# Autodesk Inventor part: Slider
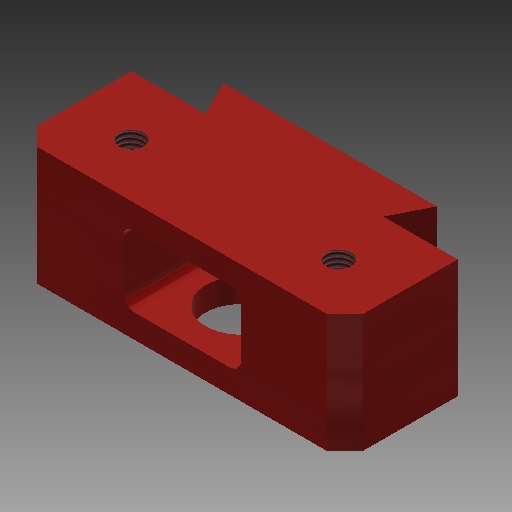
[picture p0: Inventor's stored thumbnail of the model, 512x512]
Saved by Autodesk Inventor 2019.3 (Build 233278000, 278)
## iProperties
Created: 2011-02
Part Number: Slider
Material: Glass
Document SubType Name: Modeling
Designer: landrews
Density: 2.18 g/cm^3
Appearance: Orange-Red
Mass: 44.0724 g
Surface Area: 68.5197 cm^2
Volume: 20.2167 cm^3
Author: landrews
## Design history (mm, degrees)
sketch "Sketch1"
  geometry: L1 (-27.5, 6)-(-15, 6); L2 (-15, 6)-(-18, 0); L3 (-27.5, 25)-(-27.5, 6); L4 (-27.5, 25)-(0, 25); L5 (-18, 0)-(0, 0); L6 (0, -5)-(0, 30) reference; L7 (38.5, 0)-(-38.5, 0) reference; L8 (27.5, 6)-(15, 6); L9 (15, 6)-(18, 0); L10 (27.5, 25)-(27.5, 6); L11 (27.5, 25)-(0, 25); L12 (18, 0)-(0, 0)
  constraints: 20 end point, 4 symmetric about line, 3 point on line, 2 horizontal
  dimensions: "d9" = 19 distance of L3.start L1.start; "d10" = 25 distance between parallel lines of L5 L4; "d11" = 27.5 distance between parallel lines of L6 L3; "d17" = 12.5 distance of L1.start L1.end; "d19" = 9.5 distance from line of L3 L2.end
extrude "Extrusion1" new body sketch "Sketch1" stored distance "d13" = 20; taper "d14" = 0 deg
sketch "Sketch2"
  geometry: L1 (18, 0)-(-18, 0) reference; L2 (-27.5, 25)-(27.5, 25) reference; 3 further points
  constraints: 1 midpoint, 1 vertical alignment
  dimensions: "d20" = 10 distance from line of L2 point (0, 15)
hole "Hole1" sketch "Sketch2" at (0, 15) diameter "d21" = 12; stored, may be unused: countersink angle "d25" = 90 deg, drill point angle "d27" = 118 deg; dims "d22" = 6, "d23" = 4, "d24" = 2, "d26" = 8
sketch "Sketch3"
  geometry: L1 (19.5, -16)-(35.5, -16); L2 (35.5, -4)-(19.5, -4); L3 (37.5, -14)-(37.5, -6); L4 (17.5, -6)-(17.5, -14); L5 (-11, -10)-(66, -10) reference; L6 (27.5, 4)-(27.5, -24) reference; A1 r 2 centre (35.5, -14) between (35.5, -16) and (37.5, -14); A2 r 2 centre (35.5, -6) between (37.5, -6) and (35.5, -4); A3 r 2 centre (19.5, -6) between (19.5, -4) and (17.5, -6); A4 r 2 centre (19.5, -14) between (17.5, -14) and (19.5, -16); 3 further points
  constraints: 8 end point, 8 point on circle, 8 tangent, 4 centre point, 3 equal radius, 2 midpoint, 2 parallel, 1 horizontal, 1 horizontal alignment, 1 perpendicular, 1 vertical alignment, 2 other
  dimensions: "d28" = 2 radius of A4; "d29" = 20 distance between parallel lines of L3 L4; "d30" = 12 distance between parallel lines of L1 L2
extrude "Extrusion2" cut sketch "Sketch3" distance "d35" = 16; taper "d36" = 0 deg
sketch "Sketch4"
  geometry: L1 (27.5, -25)-(-27.5, -25) reference; L2 (27.5, -6)-(27.5, -25) reference; L3 (-27.5, -25)-(-27.5, -6) reference; 3 further points
  constraints: 1 horizontal alignment
  dimensions: "d37" = 10 distance from line of L3 point (-17.5, -16); "d38" = 9 distance from line of L1 point (-17.5, -16); "d39" = 10 distance from line of L2 point (17.5, -16) (= d37)
hole "Hole2" sketch "Sketch4" at (-17.5, -16), (17.5, -16) diameter "d40" = 4.134; stored, may be unused: countersink angle "d44" = 90 deg, drill point angle "d46" = 118 deg; dims "d41" = 6, "d42" = 4, "d43" = 2, "d45" = 8
chamfer "Chamfer1" distance "d47" = 3; stored, may be unused: second distance "d48" = 2, angle "d49" = 45 deg
body "Solid1"
other parameters: "d3" = 0.5 [user parameter], "d4" = 25 [user parameter]
